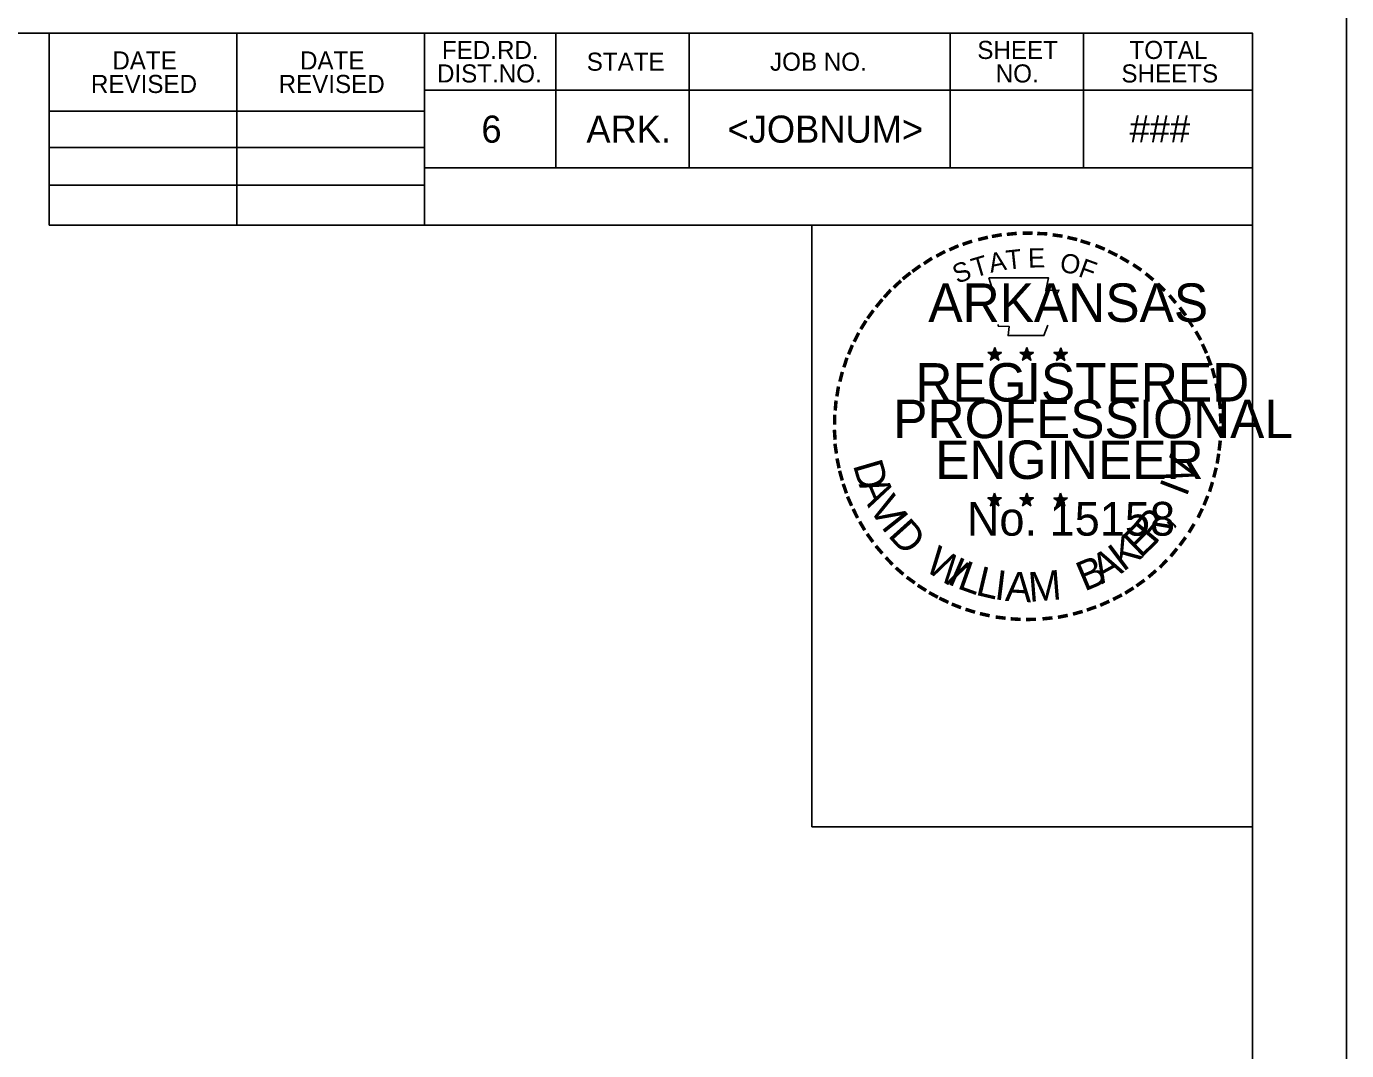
# Model space of a CAD drawing. Extents: x 1371343 to 1373043, y 378740 to 382040.
# Drawn here: x 1372692.4 to 1373042.9, y 380645.4 to 380917.3 of the extents above; entities that cross this region are included whole.
import ezdxf

# ---------------------------------------------------------------- set-up
doc = ezdxf.new("R2010")
doc.units = 0
for name, color, linetype in [('E_Existing ROW', 7, 'Continuous'), ('R_Alt Surface', 7, 'Continuous'), ('R_Alt Surface Annot', 7, 'Continuous'), ('R_Axis', 7, 'Continuous'), ('R_Axis Annot', 7, 'Continuous'), ('R_Border Prem', 7, 'Continuous'), ('R_Contour Annot', 7, 'Continuous')]:
    doc.layers.add(name, color=color, linetype=linetype)

msp = doc.modelspace()

# ---------------------------------------------------------------- linework, layer by layer
at = {"layer": 'E_Existing ROW'}
for p, q in [((1372698.46, 380864.55), (1372698.46, 380915.49)), ((1372748.28, 380864.55), (1372748.28, 380915.49)), ((1372798.11, 380915.49), (1372798.11, 380864.55)), ((1372832.99, 380915.49), (1372832.99, 380879.71)), ((1372868.39, 380915.49), (1372868.39, 380879.71)), ((1372937.64, 380915.49), (1372937.64, 380879.71)), ((1372973.04, 380915.49), (1372973.04, 380879.71)), ((1373017.92, 380900.34), (1372798.11, 380900.34)), ((1373017.92, 380900.44), (1373017.92, 380900.44)), ((1372698.46, 380894.77), (1372798.11, 380894.77)), ((1372698.46, 380885.18), (1372798.11, 380885.18)), ((1373017.92, 380879.71), (1372798.11, 380879.71)), ((1372813.21, 380879.71), (1373017.92, 380879.71)), ((1372698.46, 380875.17), (1372798.11, 380875.17)), ((1373017.92, 380864.55), (1372698.46, 380864.55))]:
    msp.add_line(p, q, dxfattribs=at)
for points in [[(1371342.92, 379840.49), (1373042.92, 379840.49), (1373042.92, 380940.49), (1371342.92, 380940.49)], [(1371367.92, 379865.49), (1373017.92, 379865.49), (1373017.92, 380915.49), (1371367.92, 380915.49)], [(1372698.46, 380864.55), (1373017.92, 380864.55), (1373017.92, 380915.49), (1372698.46, 380915.49)]]:
    msp.add_lwpolyline(points, close=True, dxfattribs=at)
at = {"layer": 'R_Axis'}
msp.add_lwpolyline([(1372900.91, 380704.83), (1373017.92, 380704.83), (1373017.92, 380864.55), (1372900.91, 380864.55)], close=True, dxfattribs=at)
at = {"layer": 'R_Axis Annot'}
msp.add_lwpolyline([(1372907.92, 380864.51), (1372908.1, 380864.51), (1372908.1, 380864.55), (1372907.92, 380864.55)], close=True, dxfattribs=at)
at = {"layer": 'R_Border Prem'}
for p, q in [((1372947.71, 380830.75), (1372949.49, 380830.18)), ((1372947.71, 380830.75), (1372949, 380830.52)), ((1372947.71, 380830.75), (1372948.92, 380830.13)), ((1372949.49, 380832.04), (1372949.28, 380830.76)), ((1372949.49, 380830.18), (1372949.49, 380832.04)), ((1372949.49, 380832.04), (1372949.74, 380830.77)), ((1372951.26, 380830.75), (1372949.49, 380830.18)), ((1372951.26, 380830.75), (1372949.8, 380830.5)), ((1372951.26, 380830.75), (1372950.22, 380830.23)), ((1372956.23, 380830.75), (1372958.01, 380830.18)), ((1372956.23, 380830.75), (1372957.52, 380830.52)), ((1372956.23, 380830.75), (1372957.44, 380830.13)), ((1372958.01, 380832.04), (1372957.8, 380830.76)), ((1372958.01, 380830.18), (1372958.01, 380832.04)), ((1372958.01, 380832.04), (1372958.26, 380830.77)), ((1372959.78, 380830.75), (1372958.01, 380830.18)), ((1372959.78, 380830.75), (1372958.32, 380830.5)), ((1372959.78, 380830.75), (1372958.74, 380830.23)), ((1372967.01, 380831.98), (1372966.8, 380830.7)), ((1372967.01, 380830.12), (1372967.01, 380831.98)), ((1372967.01, 380831.98), (1372967.26, 380830.71)), ((1372948.39, 380828.67), (1372949.49, 380830.18)), ((1372948.39, 380828.67), (1372949.03, 380829.91)), ((1372948.39, 380828.67), (1372949.48, 380829.77)), ((1372950.58, 380828.67), (1372949.48, 380829.76)), ((1372950.58, 380828.67), (1372949.49, 380830.18)), ((1372950.58, 380828.67), (1372949.88, 380830.15)), ((1372956.91, 380828.67), (1372958.01, 380830.18)), ((1372956.91, 380828.67), (1372957.55, 380829.91)), ((1372956.91, 380828.67), (1372958, 380829.77)), ((1372959.1, 380828.67), (1372958, 380829.76)), ((1372959.1, 380828.67), (1372958.01, 380830.18)), ((1372959.1, 380828.67), (1372958.4, 380830.15)), ((1372965.23, 380830.69), (1372967.01, 380830.12)), ((1372965.23, 380830.69), (1372966.52, 380830.46)), ((1372965.23, 380830.69), (1372966.44, 380830.06)), ((1372965.9, 380828.61), (1372967.01, 380830.12)), ((1372965.9, 380828.61), (1372966.55, 380829.85)), ((1372965.9, 380828.61), (1372967, 380829.71)), ((1372968.09, 380828.61), (1372967, 380829.7)), ((1372968.78, 380830.69), (1372967.01, 380830.12)), ((1372968.09, 380828.61), (1372967.01, 380830.12)), ((1372968.78, 380830.69), (1372967.32, 380830.44)), ((1372968.09, 380828.61), (1372967.39, 380830.09)), ((1372968.78, 380830.69), (1372967.74, 380830.17)), ((1372949.47, 380793.42), (1372949.26, 380792.14)), ((1372949.47, 380791.56), (1372949.47, 380793.42)), ((1372949.47, 380793.42), (1372949.72, 380792.15)), ((1372957.98, 380793.42), (1372957.78, 380792.14)), ((1372957.98, 380791.56), (1372957.98, 380793.42)), ((1372957.98, 380793.42), (1372958.23, 380792.15)), ((1372967, 380793.37), (1372966.79, 380792.09)), ((1372967, 380791.51), (1372967, 380793.37)), ((1372967, 380793.37), (1372967.25, 380792.1)), ((1372947.69, 380792.13), (1372949.47, 380791.56)), ((1372947.69, 380792.13), (1372948.98, 380791.9)), ((1372947.69, 380792.13), (1372948.9, 380791.5)), ((1372948.37, 380790.05), (1372949.47, 380791.56)), ((1372948.37, 380790.05), (1372949.01, 380791.29)), ((1372948.37, 380790.05), (1372949.46, 380791.15)), ((1372950.56, 380790.05), (1372949.46, 380791.14)), ((1372951.24, 380792.13), (1372949.47, 380791.56)), ((1372950.56, 380790.05), (1372949.47, 380791.56)), ((1372951.24, 380792.13), (1372949.78, 380791.88)), ((1372950.56, 380790.05), (1372949.86, 380791.53)), ((1372951.24, 380792.13), (1372950.2, 380791.61)), ((1372956.2, 380792.13), (1372957.98, 380791.56)), ((1372956.2, 380792.13), (1372957.5, 380791.9)), ((1372956.2, 380792.13), (1372957.41, 380791.5)), ((1372956.88, 380790.05), (1372957.98, 380791.56)), ((1372956.88, 380790.05), (1372957.53, 380791.29)), ((1372956.88, 380790.05), (1372957.97, 380791.15)), ((1372959.07, 380790.05), (1372957.97, 380791.14)), ((1372959.75, 380792.13), (1372957.98, 380791.56)), ((1372959.07, 380790.05), (1372957.98, 380791.56)), ((1372959.75, 380792.13), (1372958.3, 380791.88)), ((1372959.07, 380790.05), (1372958.37, 380791.53)), ((1372959.75, 380792.13), (1372958.71, 380791.61)), ((1372965.22, 380792.08), (1372967, 380791.51)), ((1372965.22, 380792.08), (1372966.51, 380791.85)), ((1372965.22, 380792.08), (1372966.43, 380791.45)), ((1372965.89, 380789.99), (1372967, 380791.51)), ((1372965.89, 380789.99), (1372966.54, 380791.24)), ((1372965.89, 380789.99), (1372966.99, 380791.1)), ((1372968.08, 380789.99), (1372966.99, 380791.09)), ((1372968.77, 380792.08), (1372967, 380791.51)), ((1372968.08, 380789.99), (1372967, 380791.51)), ((1372968.77, 380792.08), (1372967.31, 380791.83)), ((1372968.08, 380789.99), (1372967.38, 380791.48)), ((1372968.77, 380792.08), (1372967.73, 380791.56))]:
    msp.add_line(p, q, dxfattribs=at)
for points in [[(1372947.92, 380850.53), (1372949.29, 380846.31)], [(1372965.83, 380845.82), (1372966.55, 380847.27), (1372963.06, 380847.15), (1372963.81, 380850.53), (1372947.92, 380850.53)], [(1372950.43, 380838.17), (1372950.43, 380837.72), (1372953.3, 380837.63), (1372953.03, 380835.22), (1372962.56, 380835.22), (1372963.59, 380837.95)], [(1372958.01, 380832.04), (1372959.1, 380828.67), (1372956.23, 380830.75), (1372959.78, 380830.75), (1372956.91, 380828.67), (1372958.01, 380832.04)], [(1372967.01, 380831.98), (1372968.09, 380828.61), (1372965.23, 380830.69), (1372968.78, 380830.69), (1372965.9, 380828.61), (1372967.01, 380831.98)], [(1372949.47, 380793.42), (1372950.56, 380790.05), (1372947.69, 380792.13), (1372951.24, 380792.13), (1372948.37, 380790.05), (1372949.47, 380793.42)], [(1372957.98, 380793.42), (1372959.07, 380790.05), (1372956.2, 380792.13), (1372959.75, 380792.13), (1372956.88, 380790.05), (1372957.98, 380793.42)], [(1372967, 380793.37), (1372968.08, 380789.99), (1372965.22, 380792.08), (1372968.77, 380792.08), (1372965.89, 380789.99), (1372967, 380793.37)]]:
    msp.add_lwpolyline(points, dxfattribs=at)
for centre, radius in [((1372949.49, 380830.18), 0.878), ((1372949.49, 380830.18), 0.737), ((1372949.49, 380830.18), 0.59), ((1372958.01, 380830.18), 0.878), ((1372958.01, 380830.18), 0.737), ((1372958.01, 380830.18), 0.59), ((1372967, 380830.12), 0.878), ((1372967, 380830.12), 0.737), ((1372949.49, 380830.18), 0.505), ((1372949.49, 380830.18), 0.381), ((1372949.49, 380830.18), 0.253), ((1372949.49, 380830.18), 0.151), ((1372958.01, 380830.18), 0.505), ((1372958.01, 380830.18), 0.381), ((1372958.01, 380830.18), 0.253), ((1372958.01, 380830.18), 0.151), ((1372967, 380830.12), 0.59), ((1372967, 380830.12), 0.505), ((1372967, 380830.12), 0.381), ((1372967, 380830.12), 0.253), ((1372967, 380830.12), 0.151), ((1372949.47, 380791.56), 0.878), ((1372949.47, 380791.56), 0.737), ((1372957.98, 380791.56), 0.878), ((1372957.98, 380791.56), 0.737), ((1372966.99, 380791.5), 0.878), ((1372966.99, 380791.5), 0.737), ((1372949.47, 380791.56), 0.59), ((1372949.47, 380791.56), 0.505), ((1372949.47, 380791.56), 0.381), ((1372949.47, 380791.56), 0.253), ((1372949.47, 380791.56), 0.151), ((1372957.98, 380791.56), 0.59), ((1372957.98, 380791.56), 0.505), ((1372957.98, 380791.56), 0.381), ((1372957.98, 380791.56), 0.253), ((1372957.98, 380791.56), 0.151), ((1372966.99, 380791.5), 0.59), ((1372966.99, 380791.5), 0.505), ((1372966.99, 380791.5), 0.381), ((1372966.99, 380791.5), 0.253), ((1372966.99, 380791.5), 0.151)]:
    msp.add_circle(centre, radius, dxfattribs=at)
at = {"layer": 'R_Contour Annot'}
msp.add_lwpolyline([(1372949.49, 380832.04), (1372950.58, 380828.67), (1372947.71, 380830.75), (1372951.26, 380830.75), (1372948.39, 380828.67), (1372949.49, 380832.04)], dxfattribs=at)

# ---------------------------------------------------------------- texts
at = {"layer": 'R_Alt Surface'}
for s, p in [('6', (1372813.21, 380886.42)), ('ARK.', (1372841.08, 380886.42)), ('<JOBNUM>', (1372878.58, 380886.42)), ('###', (1372985.28, 380886.48))]:
    msp.add_text(s, height=7.2, dxfattribs=at).set_placement(p)
at = {"layer": 'R_Alt Surface Annot'}
for s, p in [('FED.RD.', (1372802.72, 380908.64)), ('SHEET', (1372944.87, 380908.64)), ('TOTAL', (1372985.28, 380908.64)), ('DATE', (1372715.21, 380905.85)), ('DATE', (1372765.04, 380905.85)), ('STATE', (1372841.17, 380905.52)), ('JOB NO.', (1372889.84, 380905.52)), ('REVISED', (1372709.53, 380899.61)), ('REVISED', (1372759.36, 380899.61)), ('DIST.NO.', (1372801.41, 380902.4)), ('NO.', (1372949.76, 380902.4)), ('SHEETS', (1372983.13, 380902.4))]:
    msp.add_text(s, height=4.8, dxfattribs=at).set_placement(p)
at = {"layer": 'R_Axis Annot'}
for s, height, p in [('PRELIMINARY', 0.013, (1372907.94, 380864.53)), ('SUBJECT TO REVISION', 0.009, (1372907.95, 380864.52))]:
    msp.add_text(s, height=height, dxfattribs=at).set_placement(p)
at = {"layer": 'R_Border Prem'}
for s, height, rotation, p in [('-', 8.16, 10.2193, (1372948.82, 380858.33)), ('-', 8.16, 5.8968, (1372952.54, 380858.89)), ('-', 8.16, 0.1862, (1372956.47, 380859.26)), ('-', 8.16, 357.743, (1372960.16, 380859.19)), ('-', 8.16, 352.1617, (1372963.96, 380858.9)), ('-', 8.16, 24.3072, (1372938.3, 380854.9)), ('-', 8.16, 19.1761, (1372941.54, 380856.27)), ('-', 8.16, 13.6302, (1372945.36, 380857.5)), ('-', 8.16, 347.2049, (1372967.62, 380858.32)), ('-', 8.16, 342.3362, (1372970.86, 380857.53)), ('-', 8.16, 337.8551, (1372974.61, 380856.4)), ('-', 8.16, 34.0636, (1372932.03, 380851.4)), ('-', 8.16, 28.7918, (1372935.08, 380853.28)), ('T', 5.1, 16.4036, (1372944.19, 380850.57)), ('A', 5.1, 11.2132, (1372948.41, 380851.85)), ('T', 5.1, 6.0228, (1372952.74, 380852.7)), ('E', 5.1, 0.8323, (1372958.37, 380853.26)), ('O', 5.1, 350.4515, (1372966.55, 380852.19)), ('F', 5.1, 340.0707, (1372971.42, 380851.03)), ('-', 8.16, 334.1211, (1372977.83, 380855.01)), ('-', 8.16, 329.6409, (1372980.78, 380853.57)), ('-', 8.16, 38.9507, (1372926.66, 380847.46)), ('-', 8.16, 36.2317, (1372929.08, 380849.38)), ('S', 5.1, 21.594, (1372939.53, 380848.88)), ('-', 8.16, 325.8627, (1372984.06, 380851.73)), ('-', 8.16, 320.5297, (1372987.17, 380849.56)), ('-', 8.16, 42.9622, (1372924.45, 380845.33)), ('-', 8.16, 315.5786, (1372990.23, 380847.07)), ('-', 8.16, 50.6142, (1372920.11, 380840.41)), ('-', 8.16, 48.4231, (1372922.16, 380842.89)), ('-', 8.16, 309.8797, (1372993.13, 380844.26)), ('-', 8.16, 54.2325, (1372918, 380837.52)), ('-', 8.16, 306.6522, (1372995.8, 380841.19)), ('-', 8.16, 58.0706, (1372916.34, 380834.83)), ('-', 7.14, 303.6753, (1372998.28, 380838.3)), ('-', 8.16, 62.8713, (1372914.75, 380831.7)), ('-', 8.16, 299.6684, (1372999.91, 380835.2)), ('-', 8.16, 67.7743, (1372913.43, 380828.59)), ('-', 8.16, 294.6628, (1373001.56, 380832.08)), ('-', 8.16, 72.3945, (1372912.31, 380825.37)), ('-', 8.16, 290.5728, (1373002.87, 380829.14)), ('-', 8.16, 75.461, (1372911.3, 380821.73)), ('-', 8.16, 285.1233, (1373004.07, 380826.18)), ('-', 8.16, 81.2013, (1372910.63, 380818.1)), ('-', 8.16, 280.5493, (1373005.09, 380822.39)), ('-', 8.16, 85.1863, (1372910.24, 380814.57)), ('-', 8.16, 276.5962, (1373005.91, 380818.48)), ('-', 8.16, 89.0622, (1372910.12, 380811)), ('-', 8.16, 274.3301, (1373006.22, 380814.8)), ('-', 8.16, 94.1959, (1372910.29, 380807.3)), ('-', 8.16, 269.9407, (1373006.39, 380811.57)), ('-', 8.16, 98.9479, (1372910.66, 380803.9)), ('-', 8.16, 263.5172, (1373006.3, 380808.18)), ('V', 7.85, 72.6573, (1373001.52, 380794.94)), ('-', 8.16, 260.9953, (1373005.93, 380804.84)), ('-', 8.16, 101.7149, (1372911.35, 380800.16)), ('-', 8.16, 105.4578, (1372912.18, 380797.12)), ('D', 7.85, 286.2848, (1372911.8, 380800.86)), ('-', 8.16, 255.7626, (1373005.37, 380801.38)), ('-', 8.16, 109.0874, (1372913.27, 380793.91)), ('A', 7.85, 292.7835, (1372913.3, 380795.75)), ('I', 7.85, 69.0301, (1373000.39, 380792.2)), ('-', 8.16, 252.8681, (1373004.45, 380797.71)), ('-', 8.16, 114.0643, (1372914.57, 380790.87)), ('V', 7.85, 300.7936, (1372915.92, 380789.74)), ('-', 8.16, 247.8887, (1373003.31, 380794.28)), ('-', 8.16, 115.7289, (1372916.12, 380787.72)), ('R', 7.85, 50.3651, (1372991.97, 380779.5)), ('-', 8.16, 244.6197, (1373001.98, 380791.07)), ('-', 8.16, 120.4471, (1372917.94, 380784.73)), ('I', 7.85, 308.3502, (1372919.13, 380784.45)), ('D', 7.85, 311.9774, (1372920.92, 380782.08)), ('E', 7.85, 44.0175, (1372988.23, 380775.89)), (',', 7.85, 57.4684, (1372995.66, 380784)), ('-', 8.16, 239.0712, (1372999.97, 380787.24)), ('-', 8.16, 125.8934, (1372920, 380781.87)), ('K', 7.85, 36.9143, (1372983.59, 380772.37)), ('-', 8.16, 233.8452, (1372997.92, 380783.91)), ('-', 8.16, 130.7181, (1372922.36, 380779.05)), ('W', 7.85, 328.0731, (1372930.5, 380773.07)), ('-', 8.16, 231.2538, (1372995.72, 380781.02)), ('-', 8.16, 134.2238, (1372924.99, 380776.27)), ('I', 7.85, 336.6877, (1372936.56, 380769.45)), ('L', 7.85, 340.3149, (1372939.26, 380768.21)), ('B', 7.85, 22.8589, (1372973.32, 380767.22)), ('A', 7.85, 28.9042, (1372977.89, 380769.13)), ('-', 8.16, 225.7653, (1372993.28, 380778.14)), ('-', 8.16, 138.9338, (1372927.67, 380773.9)), ('-', 8.16, 144.6463, (1372930.51, 380771.83)), ('L', 7.85, 346.6625, (1372944.15, 380766.45)), ('I', 7.85, 353.0101, (1372949.21, 380765.24)), ('A', 7.85, 356.6373, (1372952.15, 380764.81)), ('M', 7.85, 4.6473, (1372958.71, 380764.51)), ('-', 8.16, 221.0851, (1372990.62, 380775.55)), ('-', 8.16, 148.0898, (1372933.37, 380769.94)), ('-', 8.16, 212.2491, (1372985.09, 380771.17)), ('-', 8.16, 215.7363, (1372987.82, 380773.14)), ('-', 8.16, 151.5704, (1372936.32, 380768.28)), ('-', 8.16, 154.6002, (1372938.98, 380767.02)), ('-', 8.16, 158.5612, (1372942.16, 380765.73)), ('-', 8.16, 204.2516, (1372979.07, 380767.77)), ('-', 8.16, 207.3568, (1372982.25, 380769.4)), ('-', 8.16, 162.7983, (1372945.67, 380764.64)), ('-', 8.16, 167.5555, (1372949.31, 380763.81)), ('-', 8.16, 173.1155, (1372953.25, 380763.25)), ('-', 8.16, 185.8167, (1372964.99, 380763.46)), ('-', 8.16, 191.2858, (1372968.74, 380764.13)), ('-', 8.16, 195.4743, (1372972.46, 380765.15)), ('-', 8.16, 199.4643, (1372975.85, 380766.36)), ('-', 8.16, 176.5183, (1372957.07, 380762.98)), ('-', 8.16, 181.5918, (1372960.86, 380763.07))]:
    msp.add_text(s, height=height, rotation=rotation, dxfattribs=at).set_placement(p)
for s, height, p in [('ARKANSAS', 10.2, (1372931.87, 380838.86)), ('REGISTERED', 10.2, (1372928.41, 380817.7)), ('PROFESSIONAL', 10.1998, (1372922.56, 380807.99)), ('ENGINEER', 10.2, (1372933.71, 380797.15)), ('No. 15158', 8.961, (1372942.08, 380782.1)), ('AAMU', 0.000102, (1372957.65, 380764.48))]:
    msp.add_text(s, height=height, dxfattribs=at).set_placement(p)

doc.saveas('drawing.dxf')
